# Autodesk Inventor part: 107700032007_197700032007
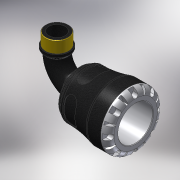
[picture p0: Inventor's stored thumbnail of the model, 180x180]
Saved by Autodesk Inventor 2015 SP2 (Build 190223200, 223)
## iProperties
Created: 2016-12
Part Number: 107700032007_197700032007
Material: PVC-Piping
Description: PLASSON 90° ELBOW WITH MALE INTEGRAL BRASS 32X3/4" SERIES 1
Document SubType Name: Modeling
Designer: KIM
Mass: 664.223 g
Surface Area: 733.008 cm^2
Volume: 474.445 cm^3
Density: 1.4 g/cm^3
Appearance: Black Cast
Author: KIM
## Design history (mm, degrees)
derived "1077.ipt"
feature "Solid1::1077.ipt"
tag "TaggingFeature1"
body "Solid1"
other parameters: "d1" = 22.68, "d2" = 32, "d4" = 58, "d8" = 49.3, "d13" = 7.2, "d14" = 7.2, "d15" = 0, "d17" = 360 deg, "d19" = 8 deg, "d20" = 0.64, "d21" = 0.64, "d22" = 8 deg, "d24" = 0, "d26" = 360 deg, "d33" = 5.8, "d43" = 45.24, "d51" = 0.58, "d54" = 11.2, "d55" = 7.04, "d57" = 14.112, "d58" = 0, "d74" = 0, "d78" = 54, "d82" = 0.64, "d115" = 360 deg, "d207" = 90 deg, "d228" = 9.52, "d247" = 1.16, "d248" = 3.24, "d268" = 27.115, "d269" = 3.24, "d270" = 81, "d276" = 26.441, "d277" = 15.5, "d278" = 29.0851, "d280" = 20.15, "d281" = 3.96615, "d283" = 23.7969, "d286" = 0, "d287" = 0, "d288" = 18.5087, "d290" = 10.72155, "d292" = 30 deg, "d294" = 2.6441, "d296" = 30 deg, "d_" = 32, "E_" = 58, "l_" = 54, "A_" = 81, "l_2" = 15.5, "R_" = 26.441, "d9" = 9, "d11" = 58, "d289" = 18.5087
